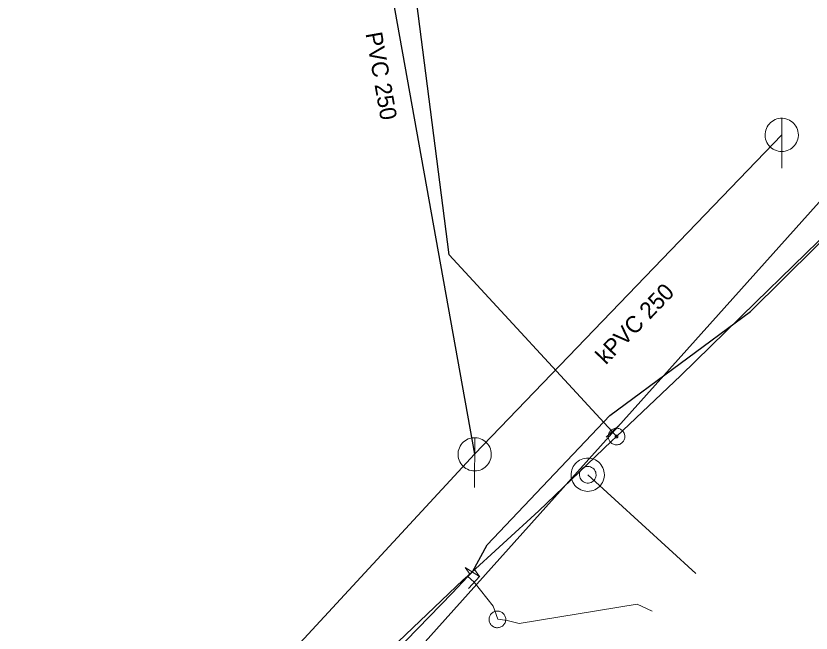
# Model space of a CAD drawing. Extents: x -779496 to -779026, y -977086 to -976624.
# Drawn here: x -779190.59 to -779142.78, y -976763.63 to -976726.5 of the extents above; entities that cross this region are included whole.
import ezdxf

# ---------------------------------------------------------------- set-up
doc = ezdxf.new("R2010")
doc.units = 0
doc.header["$LTSCALE"] = 0.4
doc.linetypes.add('MEDIUM_DASHED', pattern=[4.5, 3, -1.5])
for name, color, linetype, lineweight in [('1', 7, 'MEDIUM_DASHED', 25), ('11', 7, 'Continuous', 13), ('13', 7, 'Continuous', 13), ('14', 7, 'Continuous', 13), ('17', 7, 'Continuous', 25), ('22', 7, 'Continuous', 13), ('23', 7, 'Continuous', 13), ('34', 7, 'Continuous', 13), ('47', 7, 'Continuous', 13)]:
    doc.layers.add(name, color=color, linetype=linetype, lineweight=lineweight)

msp = doc.modelspace()

# ---------------------------------------------------------------- linework, layer by layer
at = {"layer": '11'}
msp.add_line((-779149.705, -976760.043), (-779156.211, -976754.1), dxfattribs=at)
at = {"layer": '13'}
for points in [[(-779163.039, -976760.57), (-779161.903, -976762.009), (-779161.62, -976762.78)], [(-779161.62, -976762.78), (-779161.059, -976762.859), (-779160.329, -976763.039), (-779153.239, -976761.879), (-779152.329, -976762.309)]]:
    msp.add_lwpolyline(points, dxfattribs=at)
at = {"layer": '14', "lineweight": 25}
for p, q in [((-779171, -976708.44), (-779163.01, -976752.87)), ((-779144.55, -976733.66), (-779163.01, -976752.87)), ((-779163.01, -976752.87), (-779184.76, -976776.35))]:
    msp.add_line(p, q, dxfattribs=at)
at = {"layer": '14'}
for p, q in [((-779154.739, -976751.5), (-779154.48, -976751.805)), ((-779163.45, -976760.193), (-779163.039, -976760.57))]:
    msp.add_line(p, q, dxfattribs=at)
at = {"layer": '17'}
for points in [[(-779154.48, -976751.805), (-779150.609, -976748.129), (-779146.12, -976743.739), (-779141.59, -976739.32), (-779138.37, -976736.17), (-779136.644, -976734.472), (-779134.07, -976731.94), (-779129.719, -976727.809), (-779125.59, -976723.43), (-779121.51, -976719.05), (-779117.404, -976714.654), (-779113.059, -976709.82), (-779108.91, -976705.46), (-779104.539, -976701.329), (-779101.833, -976698.611), (-779100.3, -976697.07), (-779095.68, -976693.239), (-779091.12, -976689.329), (-779086.75, -976685.239), (-779082.3, -976681.21), (-779077.739, -976677.28), (-779072.96, -976673.649), (-779068.1, -976670.079), (-779066.621, -976668.999)], [(-779189.518, -976790.412), (-779134.866, -976729.399), (-779129.046, -976723.822), (-779107.515, -976704.401), (-779072.015, -976674.642), (-779065.672, -976669.548)], [(-779154.739, -976751.5), (-779164.55, -976740.87), (-779168.91, -976706.84), (-779169.199, -976704.57), (-779169.18, -976703.55)], [(-779163.149, -976759.949), (-779162.26, -976758.32), (-779154.89, -976750.53), (-779146.43, -976744.289), (-779136.59, -976734.528), (-779132.66, -976730.629), (-779130.73, -976728.859), (-779130.026, -976728.031), (-779129.32, -976727.199)], [(-779190.59, -976791.399), (-779187.539, -976786.859), (-779184, -976781.5), (-779180.57, -976777.69), (-779176.27, -976773.379), (-779172.129, -976768.94), (-779168.039, -976764.55), (-779163.71, -976760.43), (-779163.45, -976760.193), (-779159.149, -976756.27), (-779154.78, -976752.09), (-779154.48, -976751.805)], [(-779186.859, -976792.239), (-779186.07, -976791.355), (-779182.73, -976784.316), (-779181.184, -976780.285), (-779180.028, -976777.886), (-779173.543, -976771.074), (-779171.96, -976769.05), (-779164.37, -976761.23), (-779163.412, -976760.224), (-779163.149, -976759.949)]]:
    msp.add_lwpolyline(points, dxfattribs=at)
at = {"layer": '22'}
for p, q in [((-779144.55, -976735.66), (-779144.549, -976732.66)), ((-779163.01, -976754.87), (-779163.009, -976751.87))]:
    msp.add_line(p, q, dxfattribs=at)
for points in [[(-779143.55, -976733.66), (-779143.555, -976733.551), (-779143.573, -976733.443), (-779143.603, -976733.337), (-779143.643, -976733.236), (-779143.695, -976733.139), (-779143.757, -976733.049), (-779143.829, -976732.966), (-779143.909, -976732.892), (-779143.997, -976732.826), (-779144.091, -976732.771), (-779144.191, -976732.726), (-779144.296, -976732.693), (-779144.403, -976732.671), (-779144.512, -976732.661), (-779144.622, -976732.663), (-779144.73, -976732.677), (-779144.837, -976732.702), (-779144.94, -976732.739), (-779145.038, -976732.788), (-779145.13, -976732.846), (-779145.216, -976732.915), (-779145.293, -976732.992), (-779145.362, -976733.078), (-779145.421, -976733.17), (-779145.469, -976733.268), (-779145.506, -976733.371), (-779145.532, -976733.478), (-779145.546, -976733.586), (-779145.549, -976733.696), (-779145.539, -976733.805), (-779145.518, -976733.912), (-779145.484, -976734.016), (-779145.44, -976734.116), (-779145.385, -976734.211), (-779145.319, -976734.299), (-779145.245, -976734.379), (-779145.162, -976734.451), (-779145.072, -976734.513), (-779144.976, -976734.565), (-779144.874, -976734.606), (-779144.769, -976734.636), (-779144.661, -976734.654), (-779144.551, -976734.66), (-779144.442, -976734.654), (-779144.334, -976734.636), (-779144.229, -976734.607), (-779144.127, -976734.566), (-779144.03, -976734.514), (-779143.94, -976734.452), (-779143.857, -976734.381), (-779143.782, -976734.301), (-779143.717, -976734.213), (-779143.661, -976734.119), (-779143.617, -976734.019), (-779143.583, -976733.915), (-779143.561, -976733.807), (-779143.551, -976733.698)], [(-779162.01, -976752.87), (-779162.015, -976752.761), (-779162.033, -976752.653), (-779162.063, -976752.547), (-779162.103, -976752.446), (-779162.155, -976752.349), (-779162.217, -976752.259), (-779162.289, -976752.176), (-779162.369, -976752.102), (-779162.457, -976752.036), (-779162.551, -976751.981), (-779162.651, -976751.936), (-779162.756, -976751.903), (-779162.863, -976751.881), (-779162.972, -976751.871), (-779163.082, -976751.873), (-779163.19, -976751.887), (-779163.297, -976751.912), (-779163.4, -976751.949), (-779163.498, -976751.998), (-779163.59, -976752.056), (-779163.676, -976752.125), (-779163.753, -976752.202), (-779163.822, -976752.288), (-779163.881, -976752.38), (-779163.929, -976752.478), (-779163.966, -976752.581), (-779163.992, -976752.688), (-779164.006, -976752.796), (-779164.009, -976752.906), (-779163.999, -976753.015), (-779163.978, -976753.122), (-779163.944, -976753.226), (-779163.9, -976753.326), (-779163.845, -976753.421), (-779163.779, -976753.509), (-779163.705, -976753.589), (-779163.622, -976753.661), (-779163.532, -976753.723), (-779163.436, -976753.775), (-779163.334, -976753.816), (-779163.229, -976753.846), (-779163.121, -976753.864), (-779163.011, -976753.87), (-779162.902, -976753.864), (-779162.794, -976753.846), (-779162.689, -976753.817), (-779162.587, -976753.776), (-779162.49, -976753.724), (-779162.4, -976753.662), (-779162.317, -976753.591), (-779162.242, -976753.511), (-779162.177, -976753.423), (-779162.121, -976753.329), (-779162.077, -976753.229), (-779162.043, -976753.125), (-779162.021, -976753.017), (-779162.011, -976752.908)], [(-779155.211, -976754.1), (-779155.217, -976753.991), (-779155.235, -976753.883), (-779155.265, -976753.777), (-779155.305, -976753.676), (-779155.357, -976753.579), (-779155.419, -976753.489), (-779155.491, -976753.406), (-779155.571, -976753.332), (-779155.659, -976753.266), (-779155.753, -976753.211), (-779155.853, -976753.166), (-779155.958, -976753.133), (-779156.065, -976753.111), (-779156.174, -976753.101), (-779156.284, -976753.103), (-779156.392, -976753.117), (-779156.499, -976753.142), (-779156.602, -976753.179), (-779156.7, -976753.228), (-779156.792, -976753.286), (-779156.878, -976753.355), (-779156.955, -976753.432), (-779157.024, -976753.518), (-779157.083, -976753.61), (-779157.131, -976753.708), (-779157.168, -976753.811), (-779157.194, -976753.918), (-779157.208, -976754.026), (-779157.21, -976754.136), (-779157.2, -976754.245), (-779157.179, -976754.352), (-779157.145, -976754.456), (-779157.101, -976754.556), (-779157.046, -976754.651), (-779156.98, -976754.739), (-779156.906, -976754.819), (-779156.823, -976754.891), (-779156.733, -976754.953), (-779156.637, -976755.005), (-779156.535, -976755.046), (-779156.43, -976755.076), (-779156.322, -976755.094), (-779156.212, -976755.1), (-779156.103, -976755.094), (-779155.995, -976755.076), (-779155.89, -976755.047), (-779155.788, -976755.006), (-779155.691, -976754.954), (-779155.601, -976754.892), (-779155.518, -976754.821), (-779155.443, -976754.741), (-779155.378, -976754.653), (-779155.322, -976754.559), (-779155.278, -976754.459), (-779155.244, -976754.355), (-779155.222, -976754.247), (-779155.212, -976754.138)], [(-779155.711, -976754.1), (-779155.717, -976754.023), (-779155.735, -976753.948), (-779155.764, -976753.876), (-779155.804, -976753.81), (-779155.854, -976753.75), (-779155.912, -976753.699), (-779155.977, -976753.658), (-779156.048, -976753.627), (-779156.123, -976753.608), (-779156.2, -976753.6), (-779156.278, -976753.604), (-779156.353, -976753.621), (-779156.426, -976753.648), (-779156.493, -976753.687), (-779156.553, -976753.735), (-779156.605, -976753.793), (-779156.648, -976753.857), (-779156.68, -976753.927), (-779156.701, -976754.002), (-779156.711, -976754.079), (-779156.708, -976754.156), (-779156.693, -976754.232), (-779156.667, -976754.305), (-779156.63, -976754.373), (-779156.583, -976754.434), (-779156.527, -976754.488), (-779156.463, -976754.532), (-779156.393, -976754.566), (-779156.319, -976754.588), (-779156.243, -976754.599), (-779156.165, -976754.598), (-779156.089, -976754.585), (-779156.016, -976754.56), (-779155.947, -976754.525), (-779155.885, -976754.479), (-779155.83, -976754.424), (-779155.785, -976754.361), (-779155.749, -976754.292), (-779155.725, -976754.219), (-779155.713, -976754.142)]]:
    msp.add_lwpolyline(points, close=True, dxfattribs=at)
at = {"layer": '23'}
for points in [[(-779161.143, -976762.797), (-779161.146, -976762.744), (-779161.155, -976762.692), (-779161.17, -976762.643), (-779161.189, -976762.594), (-779161.213, -976762.548), (-779161.243, -976762.504), (-779161.276, -976762.464), (-779161.313, -976762.428), (-779161.354, -976762.395), (-779161.398, -976762.367), (-779161.445, -976762.343), (-779161.495, -976762.325), (-779161.545, -976762.312), (-779161.596, -976762.305), (-779161.648, -976762.302), (-779161.702, -976762.306), (-779161.752, -976762.314), (-779161.804, -976762.329), (-779161.851, -976762.347), (-779161.898, -976762.371), (-779161.942, -976762.402), (-779161.982, -976762.435), (-779162.019, -976762.473), (-779162.052, -976762.513), (-779162.079, -976762.557), (-779162.102, -976762.605), (-779162.12, -976762.653), (-779162.133, -976762.704), (-779162.14, -976762.756), (-779162.143, -976762.808), (-779162.14, -976762.86), (-779162.131, -976762.912), (-779162.117, -976762.963), (-779162.098, -976763.011), (-779162.073, -976763.056), (-779162.044, -976763.1), (-779162.011, -976763.141), (-779161.973, -976763.178), (-779161.932, -976763.21)], [(-779161.804, -976762.329), (-779161.851, -976762.347), (-779161.898, -976762.371), (-779161.942, -976762.402), (-779161.982, -976762.435), (-779162.019, -976762.473), (-779162.052, -976762.513), (-779162.079, -976762.557), (-779162.102, -976762.605), (-779162.12, -976762.653), (-779162.133, -976762.704), (-779162.14, -976762.756), (-779162.143, -976762.808), (-779162.14, -976762.86), (-779162.131, -976762.912), (-779162.117, -976762.963), (-779162.098, -976763.011), (-779162.073, -976763.056), (-779162.044, -976763.1), (-779162.011, -976763.141), (-779161.973, -976763.178), (-779161.932, -976763.21), (-779161.889, -976763.238), (-779161.841, -976763.261), (-779161.793, -976763.28), (-779161.741, -976763.292), (-779161.69, -976763.299), (-779161.638, -976763.302), (-779161.586, -976763.298), (-779161.534, -976763.29), (-779161.483, -976763.276), (-779161.434, -976763.256), (-779161.388, -976763.232), (-779161.345, -976763.204), (-779161.305, -976763.169), (-779161.268, -976763.133), (-779161.236, -976763.092), (-779161.207, -976763.047), (-779161.184, -976763), (-779161.166, -976762.951)], [(-779161.932, -976763.21), (-779161.889, -976763.238), (-779161.841, -976763.261), (-779161.793, -976763.28), (-779161.741, -976763.292), (-779161.69, -976763.299), (-779161.638, -976763.302), (-779161.586, -976763.298), (-779161.534, -976763.29), (-779161.483, -976763.276), (-779161.434, -976763.256), (-779161.388, -976763.232), (-779161.345, -976763.204), (-779161.305, -976763.169), (-779161.268, -976763.133), (-779161.236, -976763.092), (-779161.207, -976763.047), (-779161.184, -976763), (-779161.166, -976762.951), (-779161.154, -976762.9), (-779161.146, -976762.849), (-779161.143, -976762.797), (-779161.146, -976762.744), (-779161.155, -976762.692), (-779161.17, -976762.643), (-779161.189, -976762.594), (-779161.213, -976762.548), (-779161.243, -976762.504), (-779161.276, -976762.464), (-779161.313, -976762.428), (-779161.354, -976762.395), (-779161.398, -976762.367), (-779161.445, -976762.343), (-779161.495, -976762.325), (-779161.545, -976762.312), (-779161.596, -976762.305), (-779161.648, -976762.302), (-779161.702, -976762.306), (-779161.752, -976762.314), (-779161.804, -976762.329)], [(-779161.166, -976762.951), (-779161.154, -976762.9), (-779161.146, -976762.849), (-779161.143, -976762.797)]]:
    msp.add_lwpolyline(points, dxfattribs=at)
at = {"layer": '34'}
for p, q in [((-779155.106, -976751.839), (-779154.371, -976751.161)), ((-779162.698, -976760.203), (-779163.379, -976760.935))]:
    msp.add_line(p, q, dxfattribs=at)
at = {"layer": '47'}
msp.add_line((-779163.578, -976759.674), (-779163.287, -976760.094), dxfattribs=at)
for points in [[(-779154.117, -976751.46), (-779154.155, -976751.425), (-779154.197, -976751.392), (-779154.241, -976751.366), (-779154.288, -976751.343), (-779154.338, -976751.325), (-779154.389, -976751.313), (-779154.44, -976751.307), (-779154.493, -976751.305), (-779154.545, -976751.309), (-779154.596, -976751.318), (-779154.647, -976751.333), (-779154.695, -976751.354), (-779154.741, -976751.378), (-779154.784, -976751.408), (-779154.824, -976751.442), (-779154.859, -976751.48), (-779154.892, -976751.522), (-779154.919, -976751.567), (-779154.941, -976751.613), (-779154.959, -976751.663), (-779154.971, -976751.714), (-779154.978, -976751.766), (-779154.979, -976751.818), (-779154.976, -976751.87), (-779154.966, -976751.921), (-779154.951, -976751.972), (-779154.931, -976752.021), (-779154.906, -976752.066), (-779154.876, -976752.109), (-779154.842, -976752.149), (-779154.804, -976752.184), (-779154.762, -976752.217), (-779154.718, -976752.245), (-779154.671, -976752.266), (-779154.621, -976752.284), (-779154.571, -976752.297), (-779154.519, -976752.304), (-779154.466, -976752.305), (-779154.414, -976752.301), (-779154.363, -976752.291), (-779154.312, -976752.276), (-779154.264, -976752.256), (-779154.218, -976752.231), (-779154.175, -976752.201), (-779154.135, -976752.167), (-779154.1, -976752.129), (-779154.067, -976752.087), (-779154.04, -976752.044), (-779154.018, -976751.996), (-779154, -976751.946), (-779153.987, -976751.896), (-779153.981, -976751.844), (-779153.98, -976751.792), (-779153.984, -976751.739), (-779153.993, -976751.688), (-779154.008, -976751.637), (-779154.028, -976751.59), (-779154.053, -976751.543), (-779154.083, -976751.5)], [(-779154.42, -976751.748), (-779154.426, -976751.742), (-779154.433, -976751.737), (-779154.44, -976751.733), (-779154.448, -976751.729), (-779154.456, -976751.726), (-779154.465, -976751.724), (-779154.473, -976751.723), (-779154.482, -976751.722), (-779154.49, -976751.724), (-779154.499, -976751.725), (-779154.507, -976751.727), (-779154.515, -976751.731), (-779154.522, -976751.735), (-779154.529, -976751.739), (-779154.536, -976751.745), (-779154.542, -976751.751), (-779154.547, -976751.758), (-779154.551, -976751.765), (-779154.555, -976751.773), (-779154.558, -976751.781), (-779154.56, -976751.79), (-779154.561, -976751.798), (-779154.562, -976751.807), (-779154.561, -976751.816), (-779154.559, -976751.824), (-779154.557, -976751.832), (-779154.553, -976751.84), (-779154.549, -976751.847), (-779154.545, -976751.854), (-779154.539, -976751.861), (-779154.533, -976751.867), (-779154.526, -976751.872), (-779154.519, -976751.876), (-779154.511, -976751.88), (-779154.503, -976751.883), (-779154.495, -976751.885), (-779154.486, -976751.886), (-779154.477, -976751.887), (-779154.468, -976751.886), (-779154.46, -976751.884), (-779154.452, -976751.882), (-779154.444, -976751.878), (-779154.437, -976751.874), (-779154.43, -976751.87), (-779154.423, -976751.864), (-779154.417, -976751.858), (-779154.412, -976751.851), (-779154.408, -976751.844), (-779154.404, -976751.836), (-779154.401, -976751.828), (-779154.399, -976751.82), (-779154.398, -976751.811), (-779154.397, -976751.802), (-779154.399, -976751.794), (-779154.4, -976751.785), (-779154.402, -976751.777), (-779154.406, -976751.769), (-779154.41, -976751.762), (-779154.414, -976751.755)]]:
    msp.add_lwpolyline(points, close=True, dxfattribs=at)
msp.add_lwpolyline([(-779163.578, -976759.674), (-779162.719, -976760.223), (-779163.01, -976759.803)], dxfattribs=at)

# ---------------------------------------------------------------- texts
at = {"layer": '1'}
for s, rotation, p in [('PVC 250 ', 280, (-779169.577, -976727.56)), ('kPVC 250', 46, (-779155.12, -976747.524))]:
    msp.add_text(s, height=1, rotation=rotation, dxfattribs=at).set_placement(p)

doc.saveas('drawing.dxf')
